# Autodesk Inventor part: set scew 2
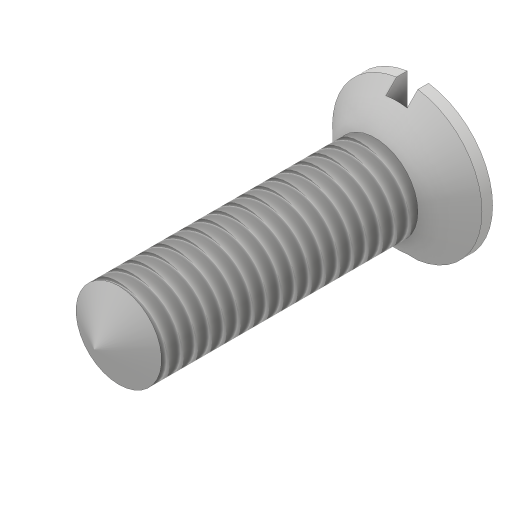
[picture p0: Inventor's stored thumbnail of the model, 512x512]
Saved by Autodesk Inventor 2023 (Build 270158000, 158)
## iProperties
Created: 2016-06
Part Number: set scew 2
Material: Generic
Document SubType Name: Modeling
Designer: CADCIM
Density: 1 g/cm^3
Appearance: Default
Mass: 0.690766 g
Surface Area: 5.88069 cm^2
Volume: 0.690766 cm^3
Author: CADCIM
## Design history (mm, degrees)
sketch "Sketch1"
  geometry: C1 r 3 at (0, 0); 1 further point
  constraints: 1 centre point, 1 coincident
  dimensions: "d0" = 6 diameter of C1
extrude "Extrusion1" new body sketch "Sketch1" distance "d1" = 18; taper "d2" = 0 deg
sketch "Sketch2"
  geometry: L1 (18, -3)-(18, 3) reference; L2 (18, 0)-(18, -3); L3 (18, -3)-(21, -6); L4 (21, -6)-(21, 0); L5 (21, 0)-(18, 0); 1 further point
  constraints: 8 end point, 2 vertical, 1 midpoint, 1 perpendicular
  dimensions: "d4" = 3 distance of L2.start L2.end; "d5" = 6 distance of L4.end L3.end; "d6" = 3 distance from line of L1.start L4
revolve "Revolution1" sketch "Sketch2" stored, may be unused: angle "d7" = 90 deg
sketch "Sketch3"
  geometry: C1 r 5.25 at (0, 0); 1 further point
  constraints: 1 centre point, 1 coincident
  dimensions: "d8" = 10.5 diameter of C1
extrude "Extrusion2" sketch "Sketch3" distance "d9" = 26.75; taper "d10" = 0 deg
sketch "Sketch4"
  geometry: L1 (-0.75, 8.347)-(0.75, 8.347); L2 (0.75, 8.347)-(0.75, -8.125); L3 (0.75, -8.125)-(-0.75, -8.125); L4 (-0.75, -8.125)-(-0.75, 8.347); L5 (0, 0)-(0, 6.165)
  constraints: 10 end point, 3 parallel, 1 horizontal, 1 perpendicular, 1 other
  dimensions: "d11" = 1.5 distance of L1.start L1.end
extrude "Extrusion3" cut sketch "Sketch4" distance "d12" = 1.5; taper "d13" = 0 deg
sketch "Sketch5"
  geometry: L1 (0, 0)-(0, 3); L2 (0, 3)-(-1.732, 0); L3 (-1.732, 0)-(0, 0); L4 (0, 3)-(0, -3) reference; 1 further point
  constraints: 6 end point, 2 midpoint, 1 perpendicular, 1 point on line, 1 vertical
  dimensions: "d21" = 60 deg angle of L2 L3; "d22" = 3 distance of L1.start L1.end
thread "Thread2" dims "d19" = 10, "d20" = 0
revolve "Revolution3" stored, may be unused: angle "d23" = 90 deg
body "Solid1"
